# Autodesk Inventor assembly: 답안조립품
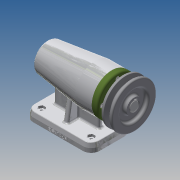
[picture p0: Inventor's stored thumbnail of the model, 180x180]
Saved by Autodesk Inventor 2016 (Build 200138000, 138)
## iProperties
Created: 2017-01
Part Number: 답안조립품
Document SubType Name: Assembly
Designer: Administrator
Author: Administrator
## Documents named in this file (12)
- D:\470107V1011\답안조립품.iam
- D:\470107V1011\본체.ipt
- D:\470107V1011\베어링 51202.ipt
- D:\470107V1011\어댑터슬리브.ipt
- D:\470107V1011\베어링 6004.ipt
- D:\470107V1011\축.ipt
- D:\470107V1011\키 5 x 5 x 16.ipt
- D:\470107V1011\V벨트풀리.ipt
- D:\470107V1011\커버.ipt
- D:\470107V1011\오일 실.ipt
- D:\470107V1011\볼트 M4 x 12.ipt
- D:\470107V1011\멈춤나사 M3x8.ipt
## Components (6 placed, 2 different names)
1. V벨트풀리:1
2. ISO 4762 M4 x 12:1
3. ISO 4762 M4 x 12:2
4. ISO 4762 M4 x 12:3
5. ISO 4762 M4 x 12:4
6. ISO 4762 M4 x 12:5
